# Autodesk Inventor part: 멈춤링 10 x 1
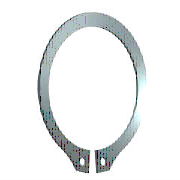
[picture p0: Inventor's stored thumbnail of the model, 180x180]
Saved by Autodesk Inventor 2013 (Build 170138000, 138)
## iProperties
IsCustomPart: 0
Created: 2015-11
Part Number: 멈춤링 10 x 1
Material: 스테인리스강
Description: 리테이닝 링(C형)
Document SubType Name: Modeling
Standard: KS B 1336
Designer: mdu
Standards Organization: KS
Language: ko-KR
Size Designation: 10 x 1
Categories: <MemberInstance><Categories><Category DisplayName="샤프트 부품" InternalName="7f7aeb1f-a693-4053-b835-cee3144e0d98" Mnemonic="SHFT"><Category DisplayName="써클립" Inter
Density: 8.08 g/cm^3
Mass: 0.434926 g
Surface Area: 1.9243 cm^2
Volume: 0.0538275 cm^3
Author: mdu
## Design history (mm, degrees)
sketch "스케치1"
  geometry: L1 (-6, 0)-(6, 0) reference; L2 (0, 20.189)-(0, -80.536) reference; L3 (-48.09, 0)-(48.09, 0) reference; L4 (-0.3, -9.791)-(-0.3, -12.791); L5 (-0.3, -6.54)-(-0.3, -13.29); L6 (-2.795, 1.6)-(3.672, 1.6); L7 (0.3, -6.54)-(0.3, -13.29); L8 (0.3, -9.791)-(0.3, -12.791); C1 r 0.6 at (-1.2, -11.486); C2 r 0.6 at (1.2, -11.486); A1 r 4.8 centre (0, -5) between (0.3, -9.791) and (-0.3, -9.791); A2 r 6.2 centre (0, -4.6) between (2.988, -10.033) and (-2.988, -10.033); A3 r 7.796 centre (0, -5) between (-1.418, -12.666) and (-0.3, -12.791); A4 r 1.2 centre (-1.2, -11.486) between (-2.383, -11.285) and (-1.418, -12.666); A5 r 1.2 centre (-3.566, -11.084) between (-2.383, -11.285) and (-2.988, -10.033); A6 r 1.2 centre (3.566, -11.084) between (2.988, -10.033) and (2.383, -11.285); A7 r 1.2 centre (1.2, -11.486) between (1.418, -12.666) and (2.383, -11.285); A8 r 7.796 centre (0, -5) between (0.3, -12.791) and (1.418, -12.666)
  constraints: 16 point on circle, 12 end point, 10 centre point, 9 symmetric about line, 5 point on line, 4 tangent, 3 coincident, 2 horizontal, 1 perpendicular, 1 vertical, 5 other
  dimensions: "d0" = 9.6 diameter of A1 (= ND); "d1" = 3 distance of L4.end L4.start (= SRB2); "d6" = 0.3 distance between parallel lines of L2 L5 (= 0.25 x SD5); "d7" = 1.6 distance between parallel lines of L6 L3 (= SRB1); "d8" = 0.4 distance of A1.centre A2.centre (= 0.25 x SRB1); "d9" = 1.2 radius of A4 (= SD5); "d10" = 1.2 radius of A5 (= SD5); "d11" = 0.9 distance from line of L4 A4.centre (= 0.75 x SD5); "d12" = 1.2 diameter of C1 (= SD5); "d13" = 1.2 diameter of C2 (= SD5); "d14" = 5 distance from line of A1.centre L1 (= 0.5 x WD)
extrude "본체" new body sketch "스케치1" distance "d2" = 1 (= SD); taper "d3" = 0 deg
workaxis "Work Axis1"
workplane "Work Plane1"
body "Solid1"
other parameters: "SD" = 1 [user parameter; used in 1 equation term], "SRB1" = 1.6 [user parameter; used in 2 equation terms], "ND" = 9.6 [user parameter; used in 1 equation term], "SRB2" = 3 [user parameter; used in 1 equation term], "SD5" = 1.2 [user parameter; used in 6 equation terms], "d15" = 0, "d16" = 0, "d17" = 0, "d41" = 0, "d42" = 0, "SD3" = 9.3 [user parameter], "WDMAX" = 11 [user parameter]
